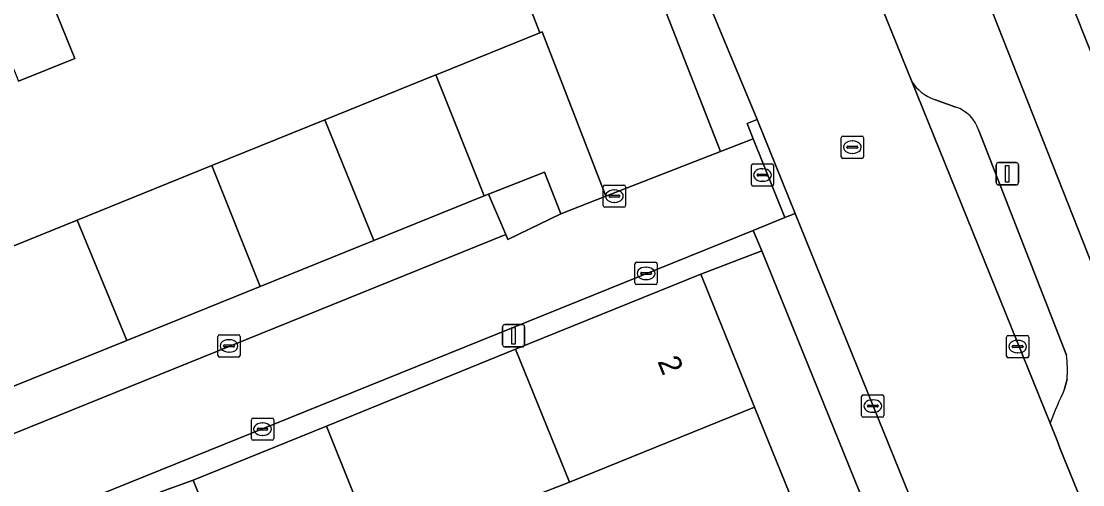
# Model space of a CAD drawing. Extents: x 162989 to 165008, y 383432 to 384338.
# Drawn here: x 163838.22 to 163885.89, y 383908.09 to 383928.91 of the extents above; entities that cross this region are included whole.
import ezdxf

# ---------------------------------------------------------------- set-up
doc = ezdxf.new("R2010")
doc.units = 0
for name, color, linetype in [('IMGEO_Brandkraan', 7, 'Continuous'), ('IMGEO_Erf', 7, 'Continuous'), ('IMGEO_Kolk', 7, 'Continuous'), ('IMGEO_Lichtmast', 7, 'Continuous'), ('IMGEO_Pand', 7, 'Continuous'), ('IMGEO_Pand_nummerreeks', 7, 'Continuous'), ('IMGEO_Parkeervlak_open', 7, 'Continuous'), ('IMGEO_Rijbaan_lokaal_open', 7, 'Continuous'), ('IMGEO_Rioolput', 7, 'Continuous'), ('IMGEO_Voetpad_open', 7, 'Continuous')]:
    doc.layers.add(name, color=color, linetype=linetype)

msp = doc.modelspace()

# ---------------------------------------------------------------- linework, layer by layer
at = {"layer": 'IMGEO_Brandkraan'}
for p, q in [((163871.01, 383921.575), (163871.01, 383922.427)), ((163871.085, 383922.501), (163871.937, 383922.501)), ((163872.011, 383922.427), (163872.011, 383921.575)), ((163871.269, 383921.995), (163871.269, 383922.007)), ((163871.707, 383921.958), (163871.309, 383921.958)), ((163871.312, 383922.044), (163871.71, 383922.044)), ((163871.498, 383922.281), (163871.523, 383922.281)), ((163871.753, 383922.007), (163871.753, 383921.995)), ((163871.937, 383921.501), (163871.085, 383921.501)), ((163871.521, 383921.721), (163871.496, 383921.721))]:
    msp.add_line(p, q, dxfattribs=at)
for points in [[(163871.01, 383921.575), (163871.01, 383922.427)], [(163871.085, 383922.501), (163871.937, 383922.501)], [(163872.011, 383922.427), (163872.011, 383921.575)], [(163871.937, 383921.501), (163871.085, 383921.501)]]:
    msp.add_lwpolyline(points, dxfattribs=at)
for centre, radius, start, end in [((163871.087, 383922.425), 0.0765, 91.552, 178.448), ((163871.087, 383922.425), 0.0765, 91.552, 178.448), ((163871.935, 383922.425), 0.0765, 1.552, 88.448), ((163871.935, 383922.425), 0.0765, 1.552, 88.448), ((163871.309, 383922.004), 0.0403, 85.8775, 175.7526), ((163871.306, 383921.994), 0.0366, 178.938, 274.7102), ((163871.71, 383922.001), 0.043, 264.8664, 352.4533), ((163871.714, 383922.006), 0.0386, 1.7309, 96.639), ((163871.087, 383921.577), 0.0765, 181.552, 268.448), ((163871.087, 383921.577), 0.0765, 181.552, 268.448), ((163871.935, 383921.577), 0.0765, 271.552, 358.448), ((163871.935, 383921.577), 0.0765, 271.552, 358.448)]:
    msp.add_arc(centre, radius, start, end, dxfattribs=at)
for centre, major_axis, ratio, start_param, end_param in [((163871.497, 383922.001), (-0.387, 0.002), 0.722429, 4.712389, 7.853982), ((163871.522, 383922.001), (-0.39, 0.002), 0.717154, 1.570796, 4.712389)]:
    msp.add_ellipse(centre, major_axis=major_axis, ratio=ratio, start_param=start_param, end_param=end_param, dxfattribs=at)
at = {"layer": 'IMGEO_Erf'}
for points in [[(163888.141, 383945.816), (163885.816, 383944.893), (163884.335, 383948.62), (163882.013, 383947.696), (163879.689, 383946.772), (163881.169, 383943.047), (163878.902, 383942.147), (163878.808, 383942.11), (163874.16, 383940.264), (163876.773, 383933.769), (163879.108, 383934.696), (163881.487, 383935.64), (163883.606, 383936.482), (163885.161, 383932.57), (163883.041, 383931.728), (163881.179, 383930.988), (163889.038, 383911.071)], [(163887.575, 383924.225), (163885.209, 383930.159), (163889.854, 383932.012)], [(163839.142, 383930.925), (163840.633, 383927.235), (163838.098, 383926.211)], [(163835.659, 383917.929), (163840.73, 383919.98), (163846.777, 383922.425), (163851.865, 383924.483), (163856.839, 383926.494), (163857.008, 383926.563), (163861.518, 383928.387), (163860.76, 383930.328)], [(163858.195, 383884.672), (163881.409, 383894.107), (163871.479, 383918.594), (163868.735, 383917.547), (163871.155, 383911.579), (163873.515, 383905.76), (163875.875, 383899.94), (163878.294, 383893.975), (163869.98, 383890.603), (163867.424, 383889.567), (163866.724, 383889.283), (163864.311, 383895.25)], [(163864.311, 383895.25), (163867.561, 383896.568), (163865.2, 383902.389), (163862.142, 383901.149), (163859.762, 383907.015), (163862.841, 383908.207), (163860.42, 383914.175), (163851.928, 383910.731), (163854.323, 383904.748), (163853.5, 383904.415), (163855.431, 383899.59), (163852.296, 383898.336), (163850.267, 383897.524), (163851.138, 383895.422), (163853.172, 383896.236), (163855.083, 383891.462), (163856.996, 383886.68), (163857.842, 383884.553)]]:
    msp.add_lwpolyline(points, dxfattribs=at)
at = {"layer": 'IMGEO_Kolk'}
for p, q in [((163864.359, 383920.625), (163864.359, 383921.477)), ((163864.434, 383921.551), (163865.286, 383921.551)), ((163865.36, 383921.477), (163865.36, 383920.625)), ((163864.618, 383921.045), (163864.618, 383921.057)), ((163865.056, 383921.008), (163864.658, 383921.008)), ((163864.661, 383921.094), (163865.059, 383921.094)), ((163864.847, 383921.331), (163864.872, 383921.331)), ((163865.102, 383921.057), (163865.102, 383921.045)), ((163865.286, 383920.551), (163864.434, 383920.551)), ((163864.87, 383920.771), (163864.845, 383920.771)), ((163865.857, 383918.084), (163866.709, 383918.084)), ((163865.782, 383917.158), (163865.782, 383918.01)), ((163866.041, 383917.578), (163866.041, 383917.59)), ((163866.084, 383917.627), (163866.482, 383917.627)), ((163866.27, 383917.864), (163866.295, 383917.864)), ((163866.525, 383917.59), (163866.525, 383917.578)), ((163866.783, 383918.01), (163866.783, 383917.158)), ((163866.479, 383917.541), (163866.081, 383917.541)), ((163866.293, 383917.304), (163866.268, 383917.304)), ((163866.709, 383917.084), (163865.857, 383917.084)), ((163847.053, 383913.901), (163847.053, 383914.753)), ((163847.128, 383914.827), (163847.98, 383914.827)), ((163848.054, 383914.753), (163848.054, 383913.901)), ((163882.468, 383913.872), (163882.468, 383914.724)), ((163882.543, 383914.798), (163883.395, 383914.798)), ((163883.469, 383914.724), (163883.469, 383913.872)), ((163847.312, 383914.321), (163847.312, 383914.333)), ((163847.75, 383914.284), (163847.352, 383914.284)), ((163847.355, 383914.37), (163847.753, 383914.37)), ((163847.541, 383914.607), (163847.566, 383914.607)), ((163847.796, 383914.333), (163847.796, 383914.321)), ((163882.727, 383914.292), (163882.727, 383914.304)), ((163883.165, 383914.255), (163882.767, 383914.255)), ((163882.77, 383914.341), (163883.168, 383914.341)), ((163882.956, 383914.578), (163882.981, 383914.578)), ((163883.211, 383914.304), (163883.211, 383914.292)), ((163847.98, 383913.827), (163847.128, 383913.827)), ((163847.564, 383914.047), (163847.539, 383914.047)), ((163883.395, 383913.798), (163882.543, 383913.798)), ((163882.979, 383914.018), (163882.954, 383914.018)), ((163875.963, 383911.203), (163875.963, 383912.055)), ((163876.038, 383912.129), (163876.89, 383912.129)), ((163876.451, 383911.909), (163876.476, 383911.909)), ((163876.964, 383912.055), (163876.964, 383911.203)), ((163876.222, 383911.623), (163876.222, 383911.635)), ((163876.66, 383911.586), (163876.262, 383911.586)), ((163876.265, 383911.672), (163876.663, 383911.672)), ((163876.706, 383911.635), (163876.706, 383911.623)), ((163848.56, 383910.164), (163848.56, 383911.016)), ((163848.635, 383911.09), (163849.487, 383911.09)), ((163849.561, 383911.016), (163849.561, 383910.164)), ((163876.89, 383911.129), (163876.038, 383911.129)), ((163876.474, 383911.349), (163876.449, 383911.349)), ((163848.819, 383910.584), (163848.819, 383910.596)), ((163849.257, 383910.547), (163848.859, 383910.547)), ((163848.862, 383910.633), (163849.26, 383910.633)), ((163849.048, 383910.87), (163849.073, 383910.87)), ((163849.303, 383910.596), (163849.303, 383910.584)), ((163849.487, 383910.09), (163848.635, 383910.09)), ((163849.071, 383910.31), (163849.046, 383910.31))]:
    msp.add_line(p, q, dxfattribs=at)
for points in [[(163864.359, 383920.625), (163864.359, 383921.477)], [(163864.434, 383921.551), (163865.286, 383921.551)], [(163865.36, 383921.477), (163865.36, 383920.625)], [(163865.286, 383920.551), (163864.434, 383920.551)], [(163865.857, 383918.084), (163866.709, 383918.084)], [(163865.782, 383917.158), (163865.782, 383918.01)], [(163866.783, 383918.01), (163866.783, 383917.158)], [(163866.709, 383917.084), (163865.857, 383917.084)], [(163847.053, 383913.901), (163847.053, 383914.753)], [(163847.128, 383914.827), (163847.98, 383914.827)], [(163848.054, 383914.753), (163848.054, 383913.901)], [(163882.468, 383913.872), (163882.468, 383914.724)], [(163882.543, 383914.798), (163883.395, 383914.798)], [(163883.469, 383914.724), (163883.469, 383913.872)], [(163847.98, 383913.827), (163847.128, 383913.827)], [(163883.395, 383913.798), (163882.543, 383913.798)], [(163875.963, 383911.203), (163875.963, 383912.055)], [(163876.038, 383912.129), (163876.89, 383912.129)], [(163876.964, 383912.055), (163876.964, 383911.203)], [(163848.56, 383910.164), (163848.56, 383911.016)], [(163848.635, 383911.09), (163849.487, 383911.09)], [(163849.561, 383911.016), (163849.561, 383910.164)], [(163876.89, 383911.129), (163876.038, 383911.129)], [(163849.487, 383910.09), (163848.635, 383910.09)]]:
    msp.add_lwpolyline(points, dxfattribs=at)
for centre, radius, start, end in [((163864.436, 383921.475), 0.0765, 91.552, 178.448), ((163864.436, 383921.475), 0.0765, 91.552, 178.448), ((163865.284, 383921.475), 0.0765, 1.552, 88.448), ((163865.284, 383921.475), 0.0765, 1.552, 88.448), ((163864.658, 383921.054), 0.0403, 85.8775, 175.7526), ((163864.655, 383921.044), 0.0366, 178.938, 274.7102), ((163865.059, 383921.051), 0.043, 264.8664, 352.4533), ((163865.063, 383921.056), 0.0386, 1.7309, 96.639), ((163864.436, 383920.627), 0.0765, 181.552, 268.448), ((163864.436, 383920.627), 0.0765, 181.552, 268.448), ((163865.284, 383920.627), 0.0765, 271.552, 358.448), ((163865.284, 383920.627), 0.0765, 271.552, 358.448), ((163865.859, 383918.008), 0.0765, 91.552, 178.448), ((163865.859, 383918.008), 0.0765, 91.552, 178.448), ((163866.707, 383918.008), 0.0765, 1.552, 88.448), ((163866.707, 383918.008), 0.0765, 1.552, 88.448), ((163866.081, 383917.587), 0.0403, 85.8775, 175.7526), ((163866.078, 383917.577), 0.0366, 178.938, 274.7102), ((163866.482, 383917.584), 0.043, 264.8664, 352.4533), ((163866.486, 383917.589), 0.0386, 1.7309, 96.639), ((163865.859, 383917.16), 0.0765, 181.552, 268.448), ((163865.859, 383917.16), 0.0765, 181.552, 268.448), ((163866.707, 383917.16), 0.0765, 271.552, 358.448), ((163866.707, 383917.16), 0.0765, 271.552, 358.448), ((163847.13, 383914.751), 0.0765, 91.552, 178.448), ((163847.13, 383914.751), 0.0765, 91.552, 178.448), ((163847.978, 383914.751), 0.0765, 1.552, 88.448), ((163847.978, 383914.751), 0.0765, 1.552, 88.448), ((163882.545, 383914.722), 0.0765, 91.552, 178.448), ((163882.545, 383914.722), 0.0765, 91.552, 178.448), ((163883.393, 383914.722), 0.0765, 1.552, 88.448), ((163883.393, 383914.722), 0.0765, 1.552, 88.448), ((163847.352, 383914.33), 0.0403, 85.8775, 175.7526), ((163847.349, 383914.32), 0.0366, 178.938, 274.7102), ((163847.753, 383914.327), 0.043, 264.8664, 352.4533), ((163847.757, 383914.332), 0.0386, 1.7309, 96.639), ((163882.767, 383914.301), 0.0403, 85.8775, 175.7526), ((163882.764, 383914.291), 0.0366, 178.938, 274.7102), ((163883.168, 383914.298), 0.043, 264.8664, 352.4533), ((163883.172, 383914.303), 0.0386, 1.7309, 96.639), ((163847.13, 383913.903), 0.0765, 181.552, 268.448), ((163847.13, 383913.903), 0.0765, 181.552, 268.448), ((163847.978, 383913.903), 0.0765, 271.552, 358.448), ((163847.978, 383913.903), 0.0765, 271.552, 358.448), ((163882.545, 383913.874), 0.0765, 181.552, 268.448), ((163882.545, 383913.874), 0.0765, 181.552, 268.448), ((163883.393, 383913.874), 0.0765, 271.552, 358.448), ((163883.393, 383913.874), 0.0765, 271.552, 358.448), ((163876.04, 383912.053), 0.0765, 91.552, 178.448), ((163876.04, 383912.053), 0.0765, 91.552, 178.448), ((163876.888, 383912.053), 0.0765, 1.552, 88.448), ((163876.888, 383912.053), 0.0765, 1.552, 88.448), ((163876.262, 383911.632), 0.0403, 85.8775, 175.7526), ((163876.259, 383911.622), 0.0366, 178.938, 274.7102), ((163876.663, 383911.629), 0.043, 264.8664, 352.4533), ((163876.667, 383911.634), 0.0386, 1.7309, 96.639), ((163848.637, 383911.014), 0.0765, 91.552, 178.448), ((163848.637, 383911.014), 0.0765, 91.552, 178.448), ((163849.485, 383911.014), 0.0765, 1.552, 88.448), ((163849.485, 383911.014), 0.0765, 1.552, 88.448), ((163876.04, 383911.205), 0.0765, 181.552, 268.448), ((163876.04, 383911.205), 0.0765, 181.552, 268.448), ((163876.888, 383911.205), 0.0765, 271.552, 358.448), ((163876.888, 383911.205), 0.0765, 271.552, 358.448), ((163848.859, 383910.593), 0.0403, 85.8775, 175.7526), ((163848.856, 383910.583), 0.0366, 178.938, 274.7102), ((163849.26, 383910.59), 0.043, 264.8664, 352.4533), ((163849.264, 383910.595), 0.0386, 1.7309, 96.639), ((163848.637, 383910.166), 0.0765, 181.552, 268.448), ((163848.637, 383910.166), 0.0765, 181.552, 268.448), ((163849.485, 383910.166), 0.0765, 271.552, 358.448), ((163849.485, 383910.166), 0.0765, 271.552, 358.448)]:
    msp.add_arc(centre, radius, start, end, dxfattribs=at)
for centre, major_axis, ratio, start_param, end_param in [((163864.846, 383921.051), (-0.387, 0.002), 0.722429, 4.712389, 7.853982), ((163864.871, 383921.051), (-0.39, 0.002), 0.717154, 1.570796, 4.712389), ((163866.269, 383917.584), (-0.387, 0.002), 0.722429, 4.712389, 7.853982), ((163866.294, 383917.584), (-0.39, 0.002), 0.717154, 1.570796, 4.712389), ((163847.54, 383914.327), (-0.387, 0.002), 0.722429, 4.712389, 7.853982), ((163847.565, 383914.327), (-0.39, 0.002), 0.717154, 1.570796, 4.712389), ((163882.955, 383914.298), (-0.387, 0.002), 0.722429, 4.712389, 7.853982), ((163882.98, 383914.298), (-0.39, 0.002), 0.717154, 1.570796, 4.712389), ((163876.45, 383911.629), (-0.387, 0.002), 0.722429, 4.712389, 7.853982), ((163876.475, 383911.629), (-0.39, 0.002), 0.717154, 1.570796, 4.712389), ((163849.047, 383910.59), (-0.387, 0.002), 0.722429, 4.712389, 7.853982), ((163849.072, 383910.59), (-0.39, 0.002), 0.717154, 1.570796, 4.712389)]:
    msp.add_ellipse(centre, major_axis=major_axis, ratio=ratio, start_param=start_param, end_param=end_param, dxfattribs=at)
at = {"layer": 'IMGEO_Lichtmast'}
for p, q in [((163882.01, 383921.659), (163882.01, 383922.459)), ((163882.01, 383922.459), (163882.01, 383921.659)), ((163882.11, 383922.559), (163882.9, 383922.559)), ((163882.9, 383922.559), (163882.11, 383922.559)), ((163883, 383922.459), (163883, 383921.659)), ((163883, 383921.659), (163883, 383922.459)), ((163882.9, 383921.559), (163882.11, 383921.559)), ((163882.11, 383921.559), (163882.9, 383921.559)), ((163859.837, 383914.384), (163859.837, 383915.184)), ((163859.837, 383915.184), (163859.837, 383914.384)), ((163859.937, 383915.284), (163860.727, 383915.284)), ((163860.727, 383915.284), (163859.937, 383915.284)), ((163860.827, 383915.184), (163860.827, 383914.384)), ((163860.827, 383914.384), (163860.827, 383915.184)), ((163860.727, 383914.284), (163859.937, 383914.284)), ((163859.937, 383914.284), (163860.727, 383914.284))]:
    msp.add_line(p, q, dxfattribs=at)
for points in [[(163882.43, 383922.434), (163882.58, 383922.434), (163882.58, 383921.684), (163882.43, 383921.684), (163882.43, 383922.434)], [(163860.257, 383915.159), (163860.407, 383915.159), (163860.407, 383914.409), (163860.257, 383914.409), (163860.257, 383915.159)]]:
    msp.add_lwpolyline(points, dxfattribs=at)
for centre, start, end in [((163882.11, 383922.459), 90, 180), ((163882.11, 383922.459), 90, 180), ((163882.9, 383922.459), 0, 90), ((163882.9, 383922.459), 360, 90), ((163882.11, 383921.659), 180, 270), ((163882.11, 383921.659), 180, 270), ((163882.9, 383921.659), 270, 0), ((163882.9, 383921.659), 270, 0), ((163859.937, 383915.184), 90, 180), ((163859.937, 383915.184), 90, 180), ((163860.727, 383915.184), 0, 90), ((163860.727, 383915.184), 360, 90), ((163859.937, 383914.384), 180, 270), ((163859.937, 383914.384), 180, 270), ((163860.727, 383914.384), 270, 0), ((163860.727, 383914.384), 270, 0)]:
    msp.add_arc(centre, 0.1, start, end, dxfattribs=at)
at = {"layer": 'IMGEO_Pand'}
for points in [[(163841.841, 383934.731), (163838.514, 383942.964), (163832.336, 383940.467), (163838.098, 383926.211), (163840.633, 383927.235), (163839.142, 383930.925), (163841.827, 383932.01), (163840.884, 383934.344)], [(163895.92, 383927.552), (163893.554, 383933.487), (163889.854, 383932.012), (163885.209, 383930.159), (163887.575, 383924.225)], [(163865.994, 383932.372), (163860.862, 383930.368), (163860.76, 383930.328), (163861.518, 383928.387), (163861.615, 383928.426), (163864.475, 383921.044), (163869.631, 383923.057)], [(163861.615, 383928.426), (163861.518, 383928.387), (163857.008, 383926.563), (163856.839, 383926.494), (163859.018, 383921.061), (163859.203, 383921.136), (163861.716, 383922.135), (163862.45, 383920.253), (163864.475, 383921.044)], [(163851.865, 383924.483), (163854.065, 383919.058), (163859.018, 383921.061), (163856.839, 383926.494)], [(163848.956, 383916.992), (163854.065, 383919.058), (163851.865, 383924.483), (163846.777, 383922.425)], [(163846.777, 383922.425), (163840.73, 383919.98), (163842.965, 383914.57), (163848.956, 383916.992)], [(163835.659, 383917.929), (163837.847, 383912.5), (163842.965, 383914.57), (163840.73, 383919.98)], [(163862.841, 383908.207), (163871.155, 383911.579), (163868.735, 383917.547), (163860.42, 383914.175)], [(163865.2, 383902.389), (163873.515, 383905.76), (163871.155, 383911.579), (163862.841, 383908.207), (163859.762, 383907.015), (163862.142, 383901.149)], [(163851.928, 383910.731), (163845.951, 383908.307), (163848.344, 383902.327), (163850.37, 383903.149), (163853.5, 383904.415), (163854.323, 383904.748)]]:
    msp.add_lwpolyline(points, close=True, dxfattribs=at)
at = {"layer": 'IMGEO_Parkeervlak_open'}
for points in [[(163878.213, 383926.2), (163884.425, 383910.857)], [(163880.188, 383925.052), (163879.235, 383925.391)], [(163885.166, 383913.911), (163881.22, 383924.002)], [(163885.078, 383912.4), (163885.192, 383912.838)]]:
    msp.add_lwpolyline(points, dxfattribs=at)
for centre, radius, start, end in [((163879.913, 383927.297), 2.023, 212.8444, 250.4263), ((163879.692, 383923.533), 1.598, 17.0808, 71.9285), ((163878.798, 383913.22), 6.405, 356.5818, 6.1943), ((163906.029, 383902.624), 23.12, 154.9853, 159.1384)]:
    msp.add_arc(centre, radius, start, end, dxfattribs=at)
at = {"layer": 'IMGEO_Rijbaan_lokaal_open'}
msp.add_lwpolyline([(163889.385, 383898.605), (163888.615, 383900.508), (163885.975, 383907.029), (163884.885, 383909.709), (163884.739, 383910.081), (163884.425, 383910.857), (163878.213, 383926.2), (163867.535, 383952.578), (163860.765, 383949.747), (163871.275, 383924.498), (163872.984, 383920.278), (163883.249, 383894.937), (163884.941, 383890.759), (163894.41, 383867.382), (163896.256, 383862.959), (163897.716, 383859.461), (163899.447, 383855.004), (163905.943, 383857.474)], close=True, dxfattribs=at)
for points in [[(163871.097, 383919.517), (163872.52, 383920.092), (163871.094, 383923.633), (163869.631, 383923.057), (163864.475, 383921.044), (163862.45, 383920.253), (163860.077, 383919.099), (163859.978, 383919.33), (163805.517, 383897.306), (163806.86, 383893.986), (163806.955, 383893.639), (163833.434, 383904.225)], [(163839.605, 383906.788), (163840.163, 383907.009), (163871.097, 383919.517)]]:
    msp.add_lwpolyline(points, dxfattribs=at)
at = {"layer": 'IMGEO_Rioolput'}
for p, q in [((163875.045, 383922.823), (163875.045, 383923.675)), ((163875.12, 383923.749), (163875.972, 383923.749)), ((163875.347, 383923.292), (163875.745, 383923.292)), ((163875.533, 383923.529), (163875.558, 383923.529)), ((163876.046, 383923.675), (163876.046, 383922.823)), ((163875.304, 383923.243), (163875.304, 383923.255)), ((163875.742, 383923.206), (163875.344, 383923.206)), ((163875.556, 383922.969), (163875.531, 383922.969)), ((163875.788, 383923.255), (163875.788, 383923.243)), ((163875.972, 383922.749), (163875.12, 383922.749))]:
    msp.add_line(p, q, dxfattribs=at)
for points in [[(163875.045, 383922.823), (163875.045, 383923.675)], [(163875.12, 383923.749), (163875.972, 383923.749)], [(163876.046, 383923.675), (163876.046, 383922.823)], [(163875.972, 383922.749), (163875.12, 383922.749)]]:
    msp.add_lwpolyline(points, dxfattribs=at)
for centre, radius, start, end in [((163875.122, 383923.673), 0.0765, 91.552, 178.448), ((163875.122, 383923.673), 0.0765, 91.552, 178.448), ((163875.344, 383923.252), 0.0403, 85.8775, 175.7526), ((163875.749, 383923.254), 0.0386, 1.7309, 96.639), ((163875.97, 383923.673), 0.0765, 1.552, 88.448), ((163875.97, 383923.673), 0.0765, 1.552, 88.448), ((163875.122, 383922.825), 0.0765, 181.552, 268.448), ((163875.122, 383922.825), 0.0765, 181.552, 268.448), ((163875.341, 383923.242), 0.0366, 178.938, 274.7102), ((163875.745, 383923.249), 0.043, 264.8664, 352.4533), ((163875.97, 383922.825), 0.0765, 271.552, 358.448), ((163875.97, 383922.825), 0.0765, 271.552, 358.448)]:
    msp.add_arc(centre, radius, start, end, dxfattribs=at)
for centre, major_axis, ratio, start_param, end_param in [((163875.532, 383923.249), (-0.387, 0.002), 0.722429, 4.712389, 7.853982), ((163875.557, 383923.249), (-0.39, 0.002), 0.717154, 1.570796, 4.712389)]:
    msp.add_ellipse(centre, major_axis=major_axis, ratio=ratio, start_param=start_param, end_param=end_param, dxfattribs=at)
at = {"layer": 'IMGEO_Voetpad_open'}
for points in [[(163867.535, 383952.578), (163878.213, 383926.2)], [(163884.425, 383910.857), (163884.739, 383910.081), (163884.885, 383909.709), (163885.975, 383907.029), (163886.39, 383907.198), (163890.075, 383908.575), (163889.038, 383911.071), (163881.179, 383930.988)], [(163879.235, 383925.391), (163880.188, 383925.052)], [(163881.22, 383924.002), (163885.166, 383913.911)], [(163860.42, 383914.175), (163868.735, 383917.547), (163871.479, 383918.594), (163871.097, 383919.517), (163840.163, 383907.009), (163839.605, 383906.788)], [(163839.963, 383905.893), (163844.488, 383907.775), (163845.951, 383908.307), (163851.928, 383910.731), (163860.42, 383914.175)], [(163885.192, 383912.838), (163885.078, 383912.4)], [(163853.049, 383890.648), (163851.138, 383895.422), (163850.267, 383897.524), (163848.344, 383902.327), (163845.951, 383908.307), (163844.488, 383907.775), (163851.158, 383891.371), (163846.62, 383889.552)]]:
    msp.add_lwpolyline(points, dxfattribs=at)
for points in [[(163860.765, 383949.747), (163859.87, 383951.466), (163858.581, 383951.074), (163861.81, 383943.084), (163865.994, 383932.372), (163869.631, 383923.057), (163871.094, 383923.633), (163870.819, 383924.317), (163871.275, 383924.498)], [(163871.275, 383924.498), (163870.819, 383924.317), (163871.094, 383923.633), (163872.52, 383920.092), (163872.984, 383920.278)], [(163861.716, 383922.135), (163859.203, 383921.136), (163859.978, 383919.33), (163860.077, 383919.099), (163862.45, 383920.253)], [(163859.978, 383919.33), (163859.203, 383921.136), (163859.018, 383921.061), (163854.065, 383919.058), (163848.956, 383916.992), (163842.965, 383914.57), (163837.847, 383912.5), (163832.966, 383910.526), (163827.707, 383908.399), (163823.081, 383906.528), (163818.239, 383904.57), (163813.375, 383902.603), (163806.022, 383899.63), (163804.877, 383898.889), (163805.517, 383897.306)], [(163872.984, 383920.278), (163872.52, 383920.092), (163871.097, 383919.517), (163871.479, 383918.594), (163881.409, 383894.107), (163882.781, 383894.749), (163883.249, 383894.937)]]:
    msp.add_lwpolyline(points, close=True, dxfattribs=at)
for centre, radius, start, end in [((163879.913, 383927.297), 2.023, 212.8444, 250.4263), ((163879.692, 383923.533), 1.598, 17.0808, 71.9285), ((163878.798, 383913.22), 6.405, 356.5818, 6.1943), ((163906.029, 383902.624), 23.12, 154.9853, 159.1384)]:
    msp.add_arc(centre, radius, start, end, dxfattribs=at)

# ---------------------------------------------------------------- texts
at = {"layer": 'IMGEO_Pand_nummerreeks'}
msp.add_text('2', height=1, rotation=292.0737, dxfattribs=at).set_placement((163866.782, 383913.637))

doc.saveas('drawing.dxf')
